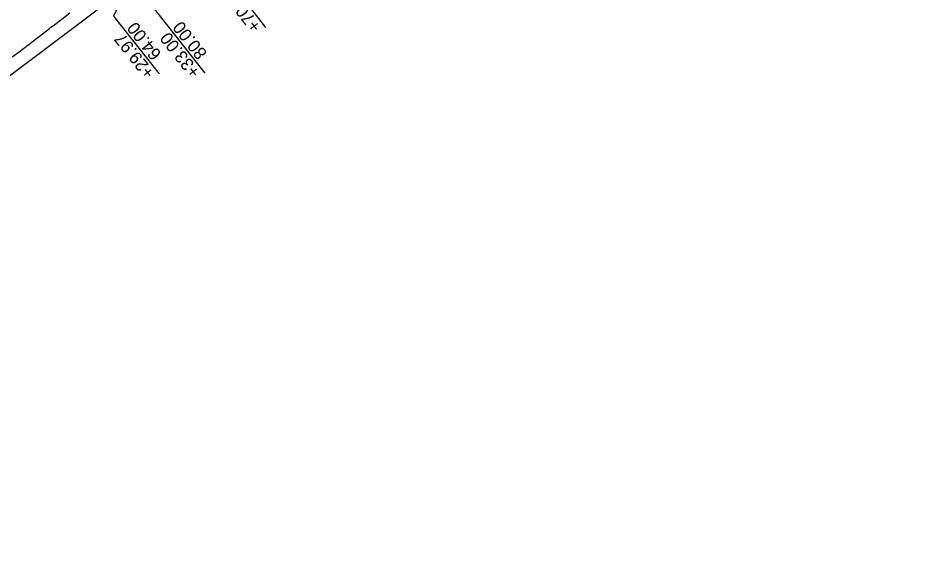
# Model space of a CAD drawing. Extents: x 1147550 to 1149124, y 2017436 to 2018779.
# Drawn here: x 1147906 to 1148333.9, y 2017436.4 to 2017688.9 of the extents above; entities that cross this region are included whole.
import ezdxf

# ---------------------------------------------------------------- set-up
doc = ezdxf.new("R2010")
doc.units = 0
for name, color, linetype in [('S_EDGE_CONCRETE', 7, 'Continuous'), ('S_ELECTRIC_UTILITIES', 7, 'Continuous'), ('S_LANDSCAPING', 7, 'Continuous'), ('S_MAILBOX', 7, 'Continuous'), ('S_SECONDARY_CTL', 7, 'Continuous')]:
    doc.layers.add(name, color=color, linetype=linetype)

msp = doc.modelspace()

# ---------------------------------------------------------------- linework, layer by layer
at = {"layer": 'S_EDGE_CONCRETE'}
msp.add_arc((1151464.82, 2013253.76), 5729.58, 124.62946, 129.43332, dxfattribs=at)
at = {"layer": 'S_ELECTRIC_UTILITIES'}
msp.add_lwpolyline([(1147958.55, 2017704.02), (1147951.54, 2017689.76), (1147973.2, 2017662.27)], dxfattribs=at)
at = {"layer": 'S_LANDSCAPING'}
for points in [[(1147999.55, 2017715.77), (1148024, 2017684.29)], [(1147970.81, 2017693.3), (1147994.96, 2017662.61)]]:
    msp.add_lwpolyline(points, dxfattribs=at)
at = {"layer": 'S_MAILBOX'}
msp.add_lwpolyline([(1147623.68, 2017436.42), (1147751.67, 2017548.43), (1147958.55, 2017704.02), (1148020.45, 2017753.36), (1148124.6, 2017828.73), (1148174.25, 2017853.51), (1148282.74, 2017941.53), (1148421.63, 2018031.39), (1148612.18, 2018197.22), (1148639.91, 2018214.06), (1148753.45, 2018306.48), (1148799.03, 2018350.69)], dxfattribs=at)
at = {"layer": 'S_SECONDARY_CTL'}
msp.add_lwpolyline([(1147903.21, 2017670.32), (1147907.2, 2017673.25), (1147908.77, 2017674.47), (1147909.72, 2017675.2), (1147910.37, 2017675.7), (1147911.12, 2017676.28), (1147915.04, 2017679.31), (1147918.96, 2017682.33), (1147920.92, 2017683.83), (1147921.49, 2017684.27), (1147922.11, 2017684.75), (1147922.89, 2017685.35), (1147926.82, 2017688.36), (1147930.75, 2017691.37)], dxfattribs=at)

# ---------------------------------------------------------------- texts
at = {"layer": 'S_ELECTRIC_UTILITIES'}
for s, p in [('64.00', (1147974.62, 2017671.78)), ('+29.97', (1147971.48, 2017662.83))]:
    msp.add_text(s, height=6, rotation=128.2338, dxfattribs=at).set_placement(p)
at = {"layer": 'S_LANDSCAPING'}
for s, rotation, p in [('+70.00', 127.8335, (1148022.23, 2017684.93)), ('80.00', 128.2035, (1147996.39, 2017672.12)), ('+33.00', 128.2035, (1147993.19, 2017663.24))]:
    msp.add_text(s, height=6, rotation=rotation, dxfattribs=at).set_placement(p)

doc.saveas('drawing.dxf')
